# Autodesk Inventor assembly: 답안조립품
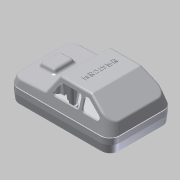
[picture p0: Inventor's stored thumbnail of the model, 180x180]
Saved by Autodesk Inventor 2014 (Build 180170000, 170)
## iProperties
Created: 2015-05
Part Number: 답안조립품
Document SubType Name: Assembly
Designer: Administrator
Author: Administrator
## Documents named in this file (4)
- C:\Documents and Settings\Administrator\바탕 화면\450508V1015\답안조립품.iam
- C:\Documents and Settings\Administrator\바탕 화면\450508V1015\본체.ipt
- C:\Documents and Settings\Administrator\바탕 화면\450508V1015\커버.ipt
- C:\Documents and Settings\Administrator\바탕 화면\450508V1015\바퀴.ipt
